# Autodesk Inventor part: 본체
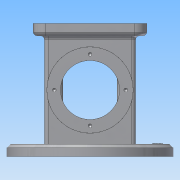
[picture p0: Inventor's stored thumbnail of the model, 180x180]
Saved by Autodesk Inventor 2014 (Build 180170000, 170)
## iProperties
Created: 2019-08
Part Number: 본체
Material: 알루미늄 6061
Document SubType Name: Modeling
Designer: net
Density: 2.71 g/cm^3
Appearance: 알루미늄 - 평지
Mass: 1047.17 g
Surface Area: 786.982 cm^2
Volume: 386.408 cm^3
Author: net
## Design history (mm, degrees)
sketch "스케치1"
  geometry: C1 r 67.5 at (0, 0); 1 further point
  constraints: 1 centre point, 1 coincident
  dimensions: "d0" = 135 diameter of C1
extrude "돌출1" new body sketch "스케치1" distance "d1" = 10; taper "d2" = 0 deg
sketch "스케치2"
  geometry: L1 (-37, 33)-(37, 33); L2 (37, 33)-(37, -33); L3 (37, -33)-(-37, -33); L4 (-37, -33)-(-37, 33); C1 r 67.5 at (0, 0) reference; 2 further points
  constraints: 8 end point, 2 midpoint, 1 horizontal, 1 horizontal alignment, 1 parallel, 1 perpendicular, 1 vertical alignment
  dimensions: "d3" = 74 distance of L1.start L1.end; "d4" = 66 distance of L1.end L2.end; "d5" = 74 distance of L2.end L3.end
extrude "돌출2" join sketch "스케치2" distance "d6" = 98; taper "d7" = 0 deg
sketch "스케치3"
  geometry: L1 (37, 33)-(-37, 33) reference; L2 (-37, 33)-(-37, -33) reference; L3 (-37, -33)-(37, -33) reference; L4 (37, -33)-(37, 33) reference; L5 (-46, 41)-(46, 41); L6 (46, 41)-(46, -41); L7 (46, -41)-(-46, -41); L8 (-46, -41)-(-46, 41); 3 further points
  constraints: 8 end point, 2 midpoint, 2 perpendicular, 1 horizontal alignment, 1 parallel, 1 vertical alignment
  dimensions: "d8" = 92 distance of L5.start L5.end; "d9" = 82 distance of L5.end L6.end; "d10" = 92 distance of L6.end L7.end
extrude "돌출3" join sketch "스케치3" distance "d11" = 10; taper "d12" = 0 deg
sketch "스케치4"
  geometry: C1 r 67.5 at (0, 0) reference; C2 r 4.5 at (0, 59); C3 r 4.5 at (-59, 0); C4 r 4.5 at (0, -59); A1 r 59 centre (0, 0) between (0, 59) and (-59, 0)
  constraints: 4 centre point, 3 point on circle, 1 coincident
  dimensions: "d13" = 118 diameter of A1; "d14" = 9 diameter of C2; "d15" = 9 diameter of C3; "d16" = 9 diameter of C4
extrude "돌출4" cut sketch "스케치4" distance "d17" = 10; taper "d18" = 0 deg
sketch "스케치5"
  geometry: L1 (-30.5, -10)-(104.5, -10) reference; L2 (37, -10)-(37, 44); C1 r 24 at (37, 44); C2 r 35 at (37, 44)
  constraints: 2 centre point, 2 coincident, 2 end point, 1 perpendicular
  dimensions: "d19" = 54 distance of L2.start L2.end; "d20" = 48 diameter of C1; "d21" = 70 diameter of C2
extrude "돌출5" cut sketch "스케치5" distance "d22" = 3; taper "d23" = 0 deg
extrude "돌출6" cut sketch "스케치5" distance "d24" = 11; taper "d25" = 0 deg
sketch "스케치6"
  geometry: C1 r 67.5 at (0, 0) reference; C2 r 25 at (0, 0)
  constraints: 1 centre point, 1 coincident
  dimensions: "d26" = 50 diameter of C2
extrude "돌출7" cut sketch "스케치6" distance "d27" = 18; taper "d28" = 0 deg
sketch "스케치7"
  geometry: L1 (-26, -26)-(26, -26); L2 (26, -26)-(26, 26); L3 (26, 26)-(-26, 26); L4 (-26, 26)-(-26, -26); L5 (-26, -26)-(26, 26); L6 (26, -26)-(-26, 26); 1 further point
  constraints: 12 end point, 2 midpoint, 2 parallel, 1 horizontal, 1 perpendicular
  dimensions: "d29" = 52 distance of L2.end L3.end; "d30" = 52 distance of L1.end L2.end
extrude "돌출8" cut sketch "스케치7" distance "d31" = 8; taper "d32" = 0 deg
sketch "스케치8"
  geometry: L1 (-22, -22)-(22, -22); L2 (22, -22)-(22, 22); L3 (22, 22)-(-22, 22); L4 (-22, 22)-(-22, -22); L5 (-22, -22)-(22, 22); L6 (22, -22)-(-22, 22); 1 further point
  constraints: 12 end point, 2 midpoint, 2 parallel, 1 horizontal, 1 perpendicular
  dimensions: "d33" = 44 distance of L2.end L3.end; "d34" = 44 distance of L1.end L2.end
extrude "돌출9" cut sketch "스케치8" distance "d35" = 74; taper "d36" = 0 deg
sketch "스케치9"
  geometry: C1 r 25 at (0, 0) reference; C2 r 12.5 at (0, 0)
  constraints: 1 centre point, 1 coincident
  dimensions: "d37" = 25 diameter of C2
extrude "돌출10" cut sketch "스케치9" distance "d38" = 74; taper "d39" = 0 deg
sketch "스케치10"
  geometry: C1 r 35 at (0, 0) reference; A1 r 29 centre (0, 0) between (0, 29) and (29, 0); 3 further points
  constraints: 4 point on circle, 1 centre point, 1 coincident
  dimensions: "d40" = 58 diameter of A1
hole "구멍1" sketch "스케치10" at (0, 29), (29, 0), (0, -29), (-29, 0) diameter "d41" = 3.242; stored, may be unused: countersink angle "d45" = 90 deg, drill point angle "d47" = 118 deg; dims "d42" = 4, "d43" = 4, "d44" = 2, "d46" = 6
fillet "모깎기1" dims "d48" = 10
sketch "스케치11"
  geometry: L1 (-36, 41)-(36, 41) reference; L2 (-36, 31)-(36, 31); L3 (36, 31)-(36, -31); A1 r 10 centre (-36, 31) between (-36, 41) and (-46, 31) reference; A2 r 10 centre (-36, -31) between (-46, -31) and (-36, -41) reference; A3 r 10 centre (36, -31) between (36, -41) and (46, -31) reference; A4 r 10 centre (36, 31) between (46, 31) and (36, 41) reference; 5 further points
  constraints: 4 coincident, 4 end point, 1 parallel, 1 perpendicular
hole "구멍2" sketch "스케치11" at (-36, 31), (-36, -31), (36, -31), (36, 31) diameter "d49" = 3.242; stored, may be unused: countersink angle "d53" = 90 deg, drill point angle "d55" = 118 deg; dims "d50" = 4, "d51" = 4, "d52" = 2, "d54" = 6
chamfer "모따기1" distance "d56" = 3; stored, may be unused: second distance "d57" = 2, angle "d58" = 45 deg
fillet "모깎기2" dims "d59" = 3
fillet "모깎기3" dims "d60" = 3
sketch "스케치12"
  geometry: L1 (10, 55)-(10, 5) reference; L2 (10, 30)-(-27, 30); L3 (-27, 30)-(-70, 30); 1 further point
  constraints: 4 end point, 2 coincident, 1 collinear, 1 perpendicular
  dimensions: "d61" = 37 distance of L2.start L2.end; "d62" = 43 distance of L3.start L3.end
hole "구멍3" sketch "스케치12" at (-27, 30), (-70, 30) diameter "d63" = 4.917; stored, may be unused: countersink angle "d67" = 90 deg, drill point angle "d69" = 118 deg; dims "d64" = 4, "d65" = 4, "d66" = 2, "d68" = 20
sketch "스케치14"
  geometry: C1 r 64.5 at (0, 0) reference; C2 r 59 at (0, 0)
  constraints: 1 centre point, 1 coincident, 1 other
  dimensions: "d71" = 118 diameter of C2
feature "엠보싱1" sketch "스케치14" dims "d2" = 0, "d8" = 92, "d9" = 82, "d10" = 92, "d72" = 0.5, "d73" = 0
chamfer "모따기2" distance "d74" = 1; stored, may be unused: second distance "d75" = 2, angle "d76" = 45 deg
fillet "모깎기4" dims "d77" = 3
fillet "모깎기5" dims "d78" = 3
fillet "모깎기6" dims "d79" = 3
node "솔리드1"
mirror "대칭1"
mirror "대칭2"
